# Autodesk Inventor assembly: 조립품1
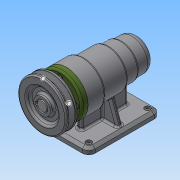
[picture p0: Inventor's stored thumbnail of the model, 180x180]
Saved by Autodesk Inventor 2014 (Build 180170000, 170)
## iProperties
Created: 2016-06
Part Number: 조립품1
Document SubType Name: Assembly
Designer: NET
Author: NET
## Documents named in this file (12)
- C:\Users\NET\Desktop\460607v1016\조립품1.iam
- C:\Users\NET\Desktop\460607v1016\본체.ipt
- C:\Users\NET\Desktop\460607v1016\축.ipt
- C:\Users\NET\Desktop\460607v1016\키 5 x 5 x 16.ipt
- C:\Users\NET\Desktop\460607v1016\어댑터슬리브.ipt
- C:\Users\NET\Desktop\460607v1016\베어링 6004.ipt
- C:\Users\NET\Desktop\460607v1016\볼트 M4 x 12.ipt
- C:\Users\NET\Desktop\460607v1016\베어링 51202.ipt
- C:\Users\NET\Desktop\460607v1016\커버.ipt
- C:\Users\NET\Desktop\460607v1016\멈춤나사 M3x8.ipt
- C:\Users\NET\Desktop\460607v1016\V벨트풀리.ipt
- C:\Users\NET\Desktop\460607v1016\오일 실.ipt
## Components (6 placed, 2 different names)
1. ISO 4762 M4 x 12:1
2. V벨트풀리:1 — 각도:2
3. ISO 4762 M4 x 12:2
4. ISO 4762 M4 x 12:3
5. ISO 4762 M4 x 12:4
6. ISO 4762 M4 x 12:5
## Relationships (1: Angle 1)
- 각도:2 [Angle]: V벨트풀리:1
